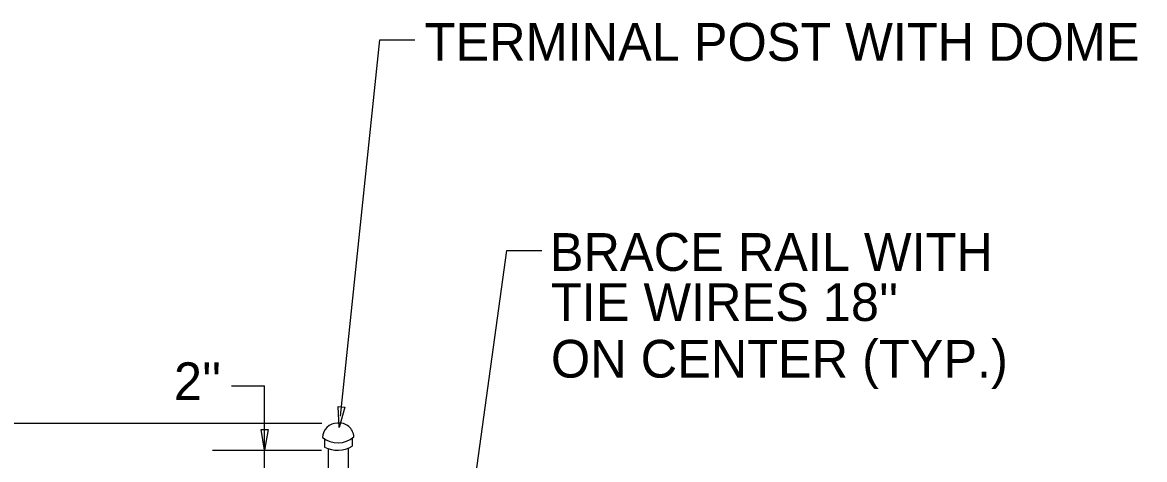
# Model space of a CAD drawing. Extents: x 0 to 2.85, y -0.1 to 1.83.
# Drawn here: x 0.2346 to 0.532, y 0.9288 to 1.0445 of the extents above; entities that cross this region are included whole.
import ezdxf

# ---------------------------------------------------------------- set-up
doc = ezdxf.new("R2010")
doc.units = 0
doc.layers.add('CT_Dimensions', color=7, linetype='Continuous')
doc.layers.add('sb_Existing Structural Steel', color=7, linetype='Continuous')

msp = doc.modelspace()

# ---------------------------------------------------------------- linework, layer by layer
at = {"layer": 'CT_Dimensions'}
for p, q in [((0.31898489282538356, 0.9402536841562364), (0.32940699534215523, 1.0399638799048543)), ((0.32940699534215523, 1.0399638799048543), (0.3386794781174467, 1.0399638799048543)), ((0.35322019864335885, 0.9133117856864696), (0.3630039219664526, 0.9841687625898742)), ((0.3630039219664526, 0.9841687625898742), (0.37227640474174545, 0.9841687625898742)), ((0.2900554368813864, 0.9482975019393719), (0.29879716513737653, 0.9482975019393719)), ((0.29883852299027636, 0.9260819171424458), (0.29879716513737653, 0.9482975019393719)), ((0.22674953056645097, 0.93842883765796), (0.3139630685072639, 0.93842883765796)), ((0.28503706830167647, 0.9312921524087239), (0.31391329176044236, 0.9312921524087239))]:
    msp.add_line(p, q, dxfattribs=at)
for points in [[(0.32010833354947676, 0.9426215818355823), (0.318548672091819, 0.9372719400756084), (0.3182890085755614, 0.9428382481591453)], [(0.29974097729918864, 0.9367358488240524), (0.29882488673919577, 0.9312393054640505), (0.2979087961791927, 0.9367358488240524)]]:
    msp.add_lwpolyline(points, close=True, dxfattribs=at)
at = {"layer": 'sb_Existing Structural Steel'}
for p, q in [((0.31471849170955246, 0.9342067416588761), (0.3147356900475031, 0.9321076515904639)), ((0.32205631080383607, 0.9344381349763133), (0.3220735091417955, 0.932339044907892)), ((0.31574716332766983, 0.8087145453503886), (0.31574716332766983, 0.9317274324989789)), ((0.32109012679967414, 0.8086073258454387), (0.32109012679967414, 0.9317672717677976))]:
    msp.add_line(p, q, dxfattribs=at)
for centre, radius, start, end in [((0.31812449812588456, 0.9344403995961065), 0.0039884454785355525, 89.88950548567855, 177.7675922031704), ((0.31863483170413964, 0.9346020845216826), 0.003859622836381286, 2.5633229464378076, 97.48293141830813), ((0.31820304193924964, 0.9399029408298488), 0.006684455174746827, 232.55698356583, 309.8978701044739), ((0.31820043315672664, 0.9386977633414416), 0.007445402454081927, 242.26690617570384, 301.3454664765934)]:
    msp.add_arc(centre, radius, start, end, dxfattribs=at)

# ---------------------------------------------------------------- texts
at = {"layer": 'CT_Dimensions'}
for s, p in [('TERMINAL POST WITH DOME CAP', (0.34125974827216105, 1.0343882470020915)), ('BRACE RAIL WITH', (0.37443530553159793, 0.9787585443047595)), ("TIE WIRES 18'' ", (0.3747220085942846, 0.9654880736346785)), ('ON CENTER (TYP.)', (0.3747220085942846, 0.9504880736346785)), ("2''", (0.2747917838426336, 0.9445302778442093))]:
    msp.add_text(s, height=0.01, dxfattribs=at).set_placement(p)

doc.saveas('drawing.dxf')
